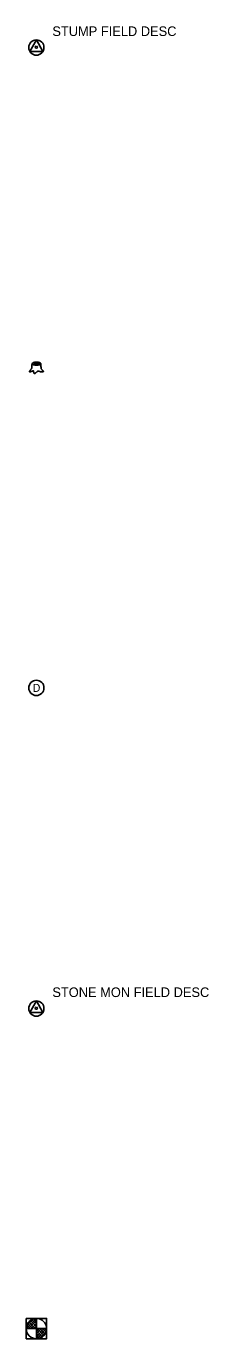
# Model space of a CAD drawing. Extents: x 98 to 2902, y -6 to 903.
# Drawn here: x 2298.4 to 2326.9, y -1.6 to 203.3 of the extents above; entities that cross this region are included whole.
import ezdxf

# ---------------------------------------------------------------- set-up
doc = ezdxf.new("R2010")
doc.units = 0
for name, color, linetype in [('V-SITE-OTLN', 7, 'Continuous'), ('V-SITE-VEGE', 7, 'Continuous'), ('V-STRM-MHOL', 7, 'Continuous'), ('V-SURV-DATA', 7, 'Continuous')]:
    doc.layers.add(name, color=color, linetype=linetype)

msp = doc.modelspace()

# ---------------------------------------------------------------- linework, layer by layer
at = {"layer": 'V-SITE-OTLN'}
for p, q in [((2300, 1.59), (2298.41, 0)), ((2298.41, 0), (2301.59, 0)), ((2298.43, 0.19), (2298.61, 0)), ((2299.53, 1.51), (2298.49, 0.47)), ((2298.51, 0.53), (2299.04, 0)), ((2298.64, 0.81), (2299.45, 0)), ((2300, 1.24), (2298.76, 0)), ((2298.8, 1.03), (2299.83, 0.02)), ((2299.07, 1.27), (2300, 0.32)), ((2300, 0.81), (2299.19, 0)), ((2299.3, 1.42), (2300, 0.72)), ((2299.57, 1.53), (2300, 1.1)), ((2300, 0.38), (2299.62, 0)), ((2300, -1.59), (2300, 1.59)), ((2300, -1.59), (2301.59, 0)), ((2300, -0.38), (2300.38, 0)), ((2300, -1.22), (2301.22, 0)), ((2300, -0.79), (2300.79, 0)), ((2301.19, -1.05), (2300.14, 0)), ((2301.34, -0.82), (2300.53, 0)), ((2301.48, -0.53), (2300.95, 0)), ((2301.57, -0.21), (2301.36, 0)), ((2300.91, -1.27), (2300, -0.34)), ((2300.68, -1.43), (2300, -0.73)), ((2300.4, -1.53), (2300, -1.11)), ((2300.47, -1.51), (2301.51, -0.47))]:
    msp.add_line(p, q, dxfattribs=at)
msp.add_lwpolyline([(2298.41, 1.59), (2298.41, -1.59), (2301.59, -1.59), (2301.59, 1.59)], close=True, dxfattribs=at)
msp.add_circle((2300, 0), 1.59, dxfattribs=at)
at = {"layer": 'V-SITE-VEGE'}
for major_axis, ratio in [((-0.699, 0), 0.366235), ((-0.456, 0), 0.345965), ((-0.188, 0), 0.37051)]:
    msp.add_ellipse((2300.02, 150.61), major_axis=major_axis, ratio=ratio, dxfattribs=at)
msp.add_open_spline([(2299.32, 150.61), (2299.32, 150.03), (2299.21, 149.77), (2298.98, 149.51), (2298.9, 149.38), (2298.9, 149.38), (2298.95, 149.33), (2299.07, 149.33), (2299.52, 149.52), (2299.52, 149.52), (2299.55, 149.44), (2299.58, 149.26), (2299.62, 149.12), (2299.66, 149.06), (2299.72, 149.03), (2299.79, 149.08), (2300.11, 149.35), (2300.22, 149.44), (2300.31, 149.44), (2300.4, 149.44), (2300.68, 149.31), (2300.85, 149.31), (2301.06, 149.34), (2301.1, 149.37), (2301.1, 149.4), (2301.07, 149.46), (2300.81, 149.72), (2300.75, 149.82), (2300.72, 149.94), (2300.72, 150.61)], degree=2, dxfattribs=at)
at = {"layer": 'V-STRM-MHOL'}
msp.add_circle((2300, 100), 1.19, dxfattribs=at)
at = {"layer": 'V-SURV-DATA'}
for p, q in [((2300, 201.14), (2298.97, 199.35)), ((2300, 201.14), (2301.03, 199.35)), ((2298.97, 199.35), (2301.03, 199.35)), ((2300, 51.14), (2298.97, 49.35)), ((2298.97, 49.35), (2301.03, 49.35)), ((2300, 51.14), (2301.03, 49.35))]:
    msp.add_line(p, q, dxfattribs=at)
for centre in [(2300, 199.95), (2300, 49.95)]:
    msp.add_circle(centre, 1.19, dxfattribs=at)
for centre in [(2300, 200), (2300, 50)]:
    msp.add_arc(centre, 0.165, 92.2877, 90.5674, dxfattribs=at)

# ---------------------------------------------------------------- texts
at = {"layer": 'V-STRM-MHOL'}
msp.add_text('D', height=1.25, dxfattribs=at).set_placement((2299.42, 99.38))
at = {"layer": 'V-SURV-DATA'}
for s, p in [('STUMP FIELD DESC', (2302.5, 201.75)), ('STONE MON FIELD DESC', (2302.5, 51.75))]:
    msp.add_text(s, height=1.5, dxfattribs=at).set_placement(p)

doc.saveas('drawing.dxf')
